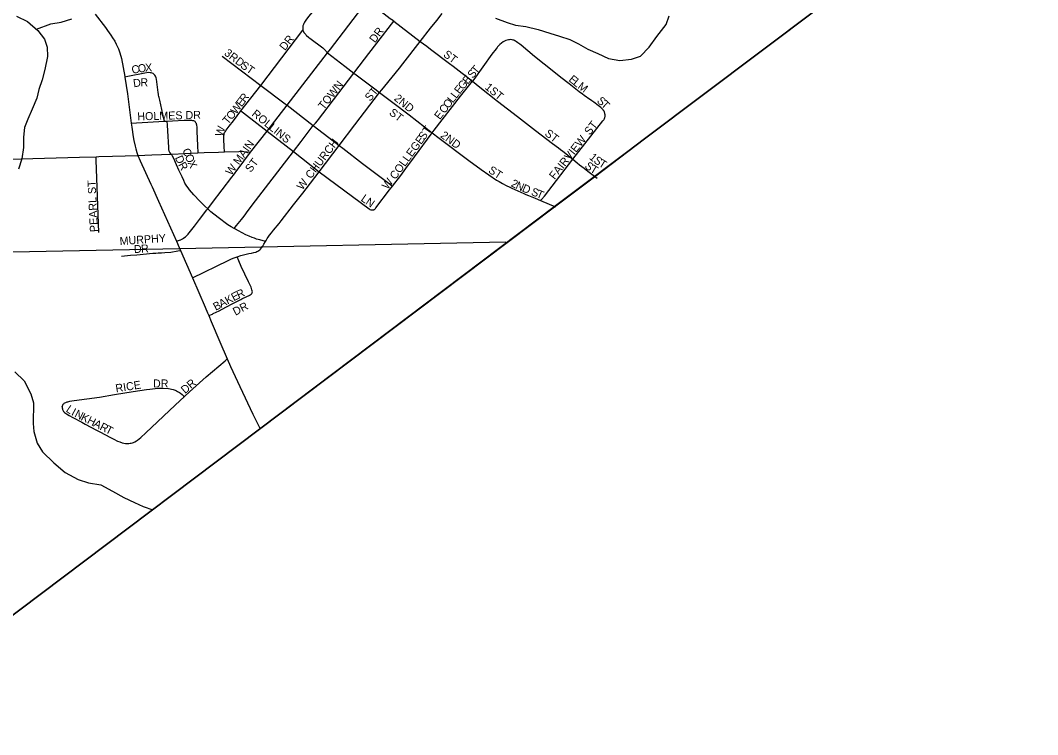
# Model space of a CAD drawing. Extents: x 1442749 to 1756758, y 235267 to 677782.
# Drawn here: x 1629919 to 1636274, y 480789 to 485248 of the extents above; entities that cross this region are included whole.
import ezdxf

# ---------------------------------------------------------------- set-up
doc = ezdxf.new("R2010")
doc.units = 0
for name, color, linetype in [('GM_X_Adjacent_County', 7, 'Continuous'), ('GM_X_City_Street', 7, 'Continuous'), ('GM_X_City_Street_Text', 7, 'Continuous'), ('GM_X_Corporation', 7, 'Continuous'), ('GM_X_County', 7, 'Continuous'), ('GM_X_Major_River', 7, 'Continuous'), ('GM_X_Minor_River', 7, 'Continuous'), ('GM_X_Rail_Line', 7, 'Continuous'), ('GM_X_State_Route', 7, 'Continuous'), ('GM_X_Township', 7, 'Continuous'), ('GM_X_Township_Subdivision', 7, 'Continuous'), ('GM_X_Township_Subdivision_Text', 7, 'Continuous')]:
    doc.layers.add(name, color=color, linetype=linetype)

msp = doc.modelspace()

# ---------------------------------------------------------------- linework, layer by layer
at = {"layer": 'GM_X_Adjacent_County'}
msp.add_lwpolyline([(1614699.6, 470049.9), (1618603.7, 472951.5), (1620523.4, 474378.3), (1621965.9, 475450.6), (1621996.8, 475474.4), (1628918.9, 480817.5), (1628957.6, 480847.4), (1631412.7, 482696.3), (1633247.9, 484078.4), (1633505.1, 484271.9), (1633818.5, 484508), (1635644.3, 485882.8), (1638041.6, 487688), (1640676.2, 489671.7), (1647133.1, 494533.2), (1648022.8, 495203.1), (1648788, 495779.1), (1655740.7, 500852.4)], dxfattribs=at)
at = {"layer": 'GM_X_City_Street'}
for points in [[(1631784.2, 485342.7), (1631744.4, 485301.8), (1631719.2, 485271.5), (1631703, 485250), (1631694.2, 485236.6), (1631690.1, 485228.8), (1631687.1, 485222.1), (1631684.3, 485213.1), (1631683.2, 485207.9), (1631682.8, 485203.8), (1631682.8, 485197.2), (1631683.9, 485187)], [(1631837.5, 485044.8), (1631855.8, 485068.1), (1632051.8, 485324.9), (1632086.5, 485369.8)], [(1632086.5, 485369.8), (1632229.8, 485260.8), (1632249.4, 485246.5), (1632252.4, 485244.1)], [(1632002.2, 484919), (1632007.7, 484926.3), (1632095.6, 485041.7), (1632252.4, 485244.1)], [(1632252.4, 485244.1), (1632416.9, 485116.8)], [(1631420.2, 484841.8), (1631683.9, 485187)], [(1631683.9, 485187), (1631687.8, 485178.6), (1631690.6, 485173.3), (1631692.1, 485171), (1631695.7, 485166.2), (1631697.7, 485163.7), (1631701.4, 485159.6), (1631705, 485155.9), (1631720.7, 485142.1), (1631727.9, 485136.4), (1631808.5, 485076), (1631815.3, 485069.9), (1631819.2, 485065.9), (1631837.5, 485044.8)], [(1632416.9, 485116.8), (1632457.5, 485086.9), (1632481.1, 485069.1), (1632598.8, 484979.3), (1632622.2, 484961.4), (1632742.7, 484867.9)], [(1632982.3, 485127.8), (1632974.7, 485127.7), (1632967.7, 485127.1), (1632959.3, 485125.5), (1632951.9, 485122.8), (1632943.5, 485118.4), (1632935.9, 485113.8), (1632924.6, 485105.7), (1632914.2, 485096.9), (1632908.6, 485091.5), (1632900.3, 485082.8), (1632896.8, 485079), (1632890.2, 485071.4), (1632863.9, 485037.6), (1632750.7, 484879), (1632742.7, 484867.9)], [(1633568.4, 484674), (1633567.6, 484676.2), (1633567.1, 484677.6), (1633566.5, 484679), (1633565.1, 484681.5), (1633564.3, 484683), (1633562.8, 484685.2), (1633562.1, 484686.2), (1633560.7, 484688.1), (1633559.5, 484689.7), (1633557, 484692.6), (1633554.1, 484695.6), (1633550.7, 484698.7), (1633545.2, 484703.3), (1633537.2, 484709.6), (1633529, 484715.9), (1633500.7, 484737.8), (1633488.8, 484746.4), (1633462.8, 484764.2), (1633455.5, 484769.2), (1633441, 484779.2), (1633430.6, 484786.7), (1633409, 484803), (1633346.6, 484851.3), (1633294.9, 484891.4), (1633251.4, 484926.1), (1633130.7, 485021.8), (1633047.7, 485092.7), (1633038.7, 485100.1), (1633027.5, 485108.7), (1633019.3, 485114.6), (1633012.4, 485119.1), (1633008.4, 485121.1), (1633001.5, 485123.9), (1632997.3, 485125.1), (1632991.2, 485126.6), (1632982.3, 485127.8)], [(1631179.2, 485024.9), (1631420.2, 484841.8)], [(1630819.3, 484618.3), (1630815.9, 484633.3), (1630789.1, 484750.1), (1630785.4, 484766.5), (1630783.8, 484773.9), (1630782.6, 484780.3), (1630781.5, 484786.6), (1630779.7, 484798.8), (1630768.2, 484880.9), (1630766.7, 484889.4), (1630765.3, 484894.8), (1630763, 484900.4), (1630759.4, 484906), (1630755.3, 484910.8), (1630751, 484914.4), (1630747.5, 484916.5), (1630742.1, 484918.8), (1630735.6, 484920.7), (1630729.9, 484921.6), (1630719.6, 484921.8), (1630697, 484918.4), (1630590.4, 484897.8), (1630572, 484894.3)], [(1631748.2, 484592.5), (1631761.9, 484606.7), (1631774.2, 484620.7), (1631781.8, 484630), (1631807.9, 484664.3), (1632002.2, 484919)], [(1631296, 484682.9), (1631420.2, 484841.8)], [(1631420.2, 484841.8), (1631572.1, 484727.7), (1631584.8, 484718.1)], [(1632491.4, 484546.3), (1632503.9, 484562.3), (1632668.8, 484774.1), (1632702, 484816.3), (1632742.7, 484867.9)], [(1632742.7, 484867.9), (1632789.1, 484831.3), (1632900.2, 484744.1), (1633024.9, 484647.8), (1633137.4, 484561), (1633242.8, 484479.1)], [(1631910.7, 484467), (1632007.5, 484596.1), (1632162.4, 484798.8)], [(1632162.4, 484798.8), (1632245.3, 484735.1), (1632347.4, 484658), (1632491.4, 484546.3)], [(1631584.8, 484718.1), (1631748.2, 484592.5)], [(1630836.4, 484619.2), (1630870.1, 484621), (1630941.8, 484624.2), (1630987.9, 484624.3), (1630994.5, 484623.6), (1630999.4, 484622), (1631003.8, 484620.6), (1631008.1, 484618.2), (1631011.2, 484614.6), (1631013.6, 484610.5), (1631016.1, 484606.3), (1631017.5, 484601.8), (1631019, 484597), (1631019.9, 484591), (1631020.8, 484584), (1631022.1, 484554.2), (1631026, 484466.1), (1631028, 484420.9)], [(1631193.7, 484427.2), (1631192.1, 484459.8), (1631189.9, 484504.3), (1631189.7, 484512.3), (1631189.7, 484518), (1631190.3, 484529.7), (1631191.2, 484536.3), (1631192.7, 484542), (1631194.7, 484547.3), (1631197.8, 484553), (1631201.4, 484558.4), (1631204.6, 484562.6), (1631210.9, 484570.3), (1631224, 484586.7), (1631250.5, 484621), (1631296, 484682.9)], [(1631296, 484682.9), (1631312.7, 484670), (1631459.9, 484556.3)], [(1630611.8, 484607.2), (1630643.4, 484608.8), (1630819.3, 484618.3)], [(1630819.3, 484618.3), (1630836.4, 484619.2)], [(1630860.4, 484413.1), (1630852.5, 484423.2), (1630848.5, 484432), (1630846.6, 484441.6), (1630845.3, 484454.6), (1630840.6, 484559.1), (1630838.2, 484594), (1630836.4, 484619.2)], [(1631625.6, 484430.2), (1631673.2, 484492.9), (1631748.2, 484592.5)], [(1631748.2, 484592.5), (1631873, 484496.5), (1631910.7, 484467)], [(1631459.9, 484556.3), (1631625.6, 484430.2)], [(1632244.5, 484213.7), (1632296.2, 484279.9), (1632325.9, 484322.9), (1632381.1, 484396.3), (1632491.4, 484546.3)], [(1632491.4, 484546.3), (1632534.2, 484513.1), (1632720.8, 484373.7), (1632797.2, 484317.1), (1632894.3, 484249.5)], [(1631785.9, 484301.6), (1631910.7, 484467)], [(1631910.7, 484467), (1631932.3, 484450.1), (1632057, 484354.4), (1632222, 484230.7), (1632244.5, 484213.7)], [(1630408.4, 483922.9), (1630392.4, 484375.8), (1630391.7, 484397)], [(1631089, 484071.8), (1631070.1, 484088.7), (1631039.9, 484118.6), (1631001.8, 484159.2), (1630976.3, 484189.3), (1630967.1, 484202), (1630958.9, 484213.1), (1630947.1, 484232.8), (1630940, 484247.5), (1630928.5, 484271.2), (1630909.7, 484313.2), (1630895, 484346.3), (1630877.6, 484385.2), (1630870.1, 484399.7), (1630864.3, 484408.5), (1630860.4, 484413.1)], [(1631089, 484071.8), (1631118.9, 484110.7), (1631240.3, 484268.9), (1631249.2, 484280.8), (1631261.3, 484297), (1631273.2, 484313.1), (1631357.1, 484425.9)], [(1631253.8, 483948.5), (1631269, 483967.3), (1631299.7, 484004.9), (1631308, 484015.7), (1631322.2, 484034.1), (1631331.4, 484046.2), (1631367.2, 484094.2), (1631449.8, 484202), (1631625.6, 484430.2)], [(1631625.6, 484430.2), (1631785.9, 484301.6)], [(1631450.4, 483868.1), (1631453.7, 483873.6), (1631461.4, 483885.9), (1631467.6, 483895.6), (1631475.6, 483906.9), (1631487.6, 483922.2), (1631500.9, 483939), (1631534.7, 483980.7), (1631548, 483997.5), (1631625.2, 484096.2), (1631683.5, 484169.7), (1631703.6, 484195.5), (1631785.9, 484301.6)], [(1631785.9, 484301.6), (1632098.6, 484070.8), (1632102.8, 484068.3), (1632107.6, 484066), (1632112.7, 484064.7), (1632116.2, 484064.4), (1632122.1, 484064.4)], [(1632122.1, 484064.4), (1632126.4, 484065.7), (1632129, 484066.8), (1632130.4, 484067.6), (1632132, 484068.7), (1632134, 484070.2), (1632135.7, 484071.7), (1632137.1, 484073.1), (1632140.1, 484076.9), (1632225.8, 484189.7), (1632244.5, 484213.7)], [(1630895, 483869), (1630913.8, 483876.1), (1630920.2, 483878.9), (1630923.8, 483880.6), (1630927.6, 483882.5), (1630932.6, 483885.2), (1630937.5, 483888.2), (1630940.5, 483890.3), (1630949.4, 483897), (1630953.7, 483900.7), (1630957.8, 483904.5), (1630962.4, 483909.2), (1630966.4, 483913.6), (1630970.9, 483918.7), (1630973.3, 483921.7), (1631006.1, 483964), (1631037.3, 484004.4), (1631083.7, 484064.9), (1631089, 484071.8)], [(1631253.8, 483948.5), (1631234.9, 483958.8), (1631215.6, 483971.1), (1631155.3, 484016.7), (1631109.2, 484053.8), (1631089, 484071.8)], [(1631450.4, 483868.1), (1631413.9, 483877.6), (1631394.8, 483882.6), (1631381.1, 483887.6), (1631367.1, 483892.8), (1631348.5, 483901.1), (1631328.1, 483910.2), (1631281.1, 483933.7), (1631261.8, 483944.2), (1631253.8, 483948.5)], [(1631273.2, 483772.8), (1631295.7, 483780.4), (1631312.7, 483785), (1631345.4, 483792.2), (1631362.3, 483795.6), (1631377.7, 483798.6), (1631388.8, 483801.8), (1631397, 483804.7), (1631402.1, 483807.2), (1631408.8, 483811.5), (1631413.7, 483815.5), (1631419.2, 483820.6), (1631425.4, 483827.9), (1631432.8, 483838.9), (1631439.8, 483850.2), (1631450.4, 483868.1)], [(1630551.5, 483775.9), (1630569, 483778.3), (1630587, 483780.7), (1630606.3, 483782.2), (1630645.6, 483785.2), (1630746.5, 483794), (1630765.2, 483795.1), (1630779.1, 483795.9), (1630800.8, 483797.2), (1630821.5, 483798.4), (1630858.9, 483801.8), (1630903.2, 483808.8), (1630920.1, 483811.5)], [(1630994, 483641.6), (1631217, 483748.9), (1631234.5, 483756.9), (1631248.3, 483763), (1631260.1, 483767.8), (1631272.2, 483772.5), (1631273.2, 483772.8)], [(1631095.3, 483404.9), (1631118.2, 483414.5), (1631124.2, 483417), (1631159.7, 483434), (1631179.8, 483444.8), (1631238.1, 483475.3), (1631296.2, 483506.4), (1631301.8, 483509.4), (1631307.3, 483512.1), (1631351.6, 483533.3), (1631355.3, 483535.1), (1631361.3, 483539), (1631364.8, 483542.4), (1631366.7, 483546.1), (1631367.8, 483549.2), (1631367.9, 483552.4), (1631367.2, 483558.7), (1631365.1, 483566.5), (1631363, 483574.6), (1631360.5, 483581.4), (1631357.4, 483589.9), (1631344.2, 483616.4), (1631298.8, 483711.1), (1631283.7, 483747.5), (1631273.2, 483772.8)], [(1630943.6, 482899.6), (1630975, 482928.5), (1631080.3, 483022.5), (1631197.5, 483122.9), (1631211.3, 483134.7)], [(1630180.6, 482834.8), (1630182.3, 482842.5), (1630183.6, 482846.6), (1630184.4, 482848.4), (1630186.8, 482852.2), (1630189.3, 482854.9), (1630192.9, 482858.1), (1630197.1, 482860.7), (1630202, 482863), (1630206, 482864.7), (1630211.5, 482866.6), (1630214.2, 482867.4), (1630221.5, 482869), (1630228.2, 482870.3), (1630239.4, 482872.1), (1630254.5, 482874.4), (1630413.6, 482896.6), (1630507.6, 482911.3), (1630624.3, 482930), (1630706.3, 482942.5), (1630727.6, 482945.2), (1630778, 482950.8), (1630797, 482951.8), (1630811, 482952.1), (1630844.6, 482949.4), (1630854.1, 482948), (1630863.5, 482946), (1630873.3, 482943.2), (1630886.4, 482938.6), (1630893.2, 482935.5), (1630900.8, 482931.5), (1630912.6, 482924.1), (1630918.4, 482919.9), (1630929, 482911.6), (1630937.2, 482904.8), (1630943.6, 482899.6)], [(1630180.6, 482834.8), (1630180.5, 482829.9), (1630180.8, 482826.1), (1630181.1, 482824.5), (1630181.7, 482821), (1630182.3, 482818.6), (1630183.4, 482815.5), (1630185.1, 482812), (1630188.7, 482806.7), (1630194.6, 482800.7), (1630206.4, 482791.4), (1630224, 482780.8), (1630246, 482768.6), (1630301.8, 482739.2), (1630324.5, 482727.2), (1630395.1, 482689.7), (1630414.2, 482679.5), (1630482.5, 482643.1), (1630501.8, 482633.4), (1630526.1, 482621.9), (1630540.8, 482616), (1630555, 482611.1), (1630575.1, 482607.4), (1630586.2, 482606.5), (1630596.8, 482606.8), (1630604.8, 482607.8), (1630611.4, 482609.1), (1630618.5, 482611.1), (1630625.2, 482613.6), (1630633.5, 482617.4), (1630644, 482623.1), (1630650.5, 482627.4), (1630660.3, 482634.9), (1630670.3, 482643.4), (1630701.7, 482673.2), (1630885.8, 482846.3), (1630943.6, 482899.6)]]:
    msp.add_lwpolyline(points, dxfattribs=at)
at = {"layer": 'GM_X_Corporation'}
msp.add_lwpolyline([(1635210.5, 485557.9), (1633823.1, 484511.4), (1633262.6, 484089.3), (1631412.7, 482696.3), (1628918.9, 480818.3), (1629029.5, 483037.3), (1629422.5, 483023.6), (1629418.1, 482896.7), (1629805, 482944.2), (1629128.1, 483732.4), (1629133.5, 483814.4), (1627617.6, 483785.3), (1627690.6, 485417.7)], dxfattribs=at)
at = {"layer": 'GM_X_County'}
msp.add_lwpolyline([(1655740.7, 500852.4), (1648788, 495779.1), (1648022.8, 495203.1), (1647133.1, 494533.2), (1640676.2, 489671.7), (1638041.6, 487688), (1635644.3, 485882.8), (1633818.5, 484508), (1633505.1, 484271.9), (1633247.9, 484078.4), (1631412.7, 482696.3), (1628957.6, 480847.4), (1628918.9, 480817.5), (1621996.8, 475474.4), (1621965.9, 475450.6), (1620523.4, 474378.3), (1618603.7, 472951.5), (1614699.6, 470049.9)], dxfattribs=at)
at = {"layer": 'GM_X_Major_River'}
for points in [[(1629893.5, 485273.8), (1629963.2, 485240.8), (1630028.5, 485185.9), (1630069.8, 485131.3), (1630087.1, 485081), (1630088.3, 485022.9), (1630071.2, 484941), (1630054.4, 484877.1), (1630033.5, 484817.3), (1630020.8, 484763.4), (1629991.8, 484693.6), (1629965, 484631.9), (1629944.3, 484580.1), (1629937.4, 484518.1), (1629938.6, 484454), (1629927.6, 484384), (1629906.7, 484318.2)], [(1629883.8, 483054.5), (1629943.1, 482997.7), (1629984, 482917), (1630001.3, 482860.7), (1629999.6, 482730.5), (1630002.9, 482680.4), (1630023.9, 482608), (1630057.2, 482553.5), (1630128.4, 482486.5), (1630197.6, 482425.5), (1630279.1, 482382.4), (1630344.9, 482361.5), (1630420.8, 482348.5), (1630494.3, 482309.5), (1630565.8, 482268.5), (1630631.5, 482237.6), (1630685.2, 482212.9), (1630745.2, 482192.1)]]:
    msp.add_lwpolyline(points, dxfattribs=at)
at = {"layer": 'GM_X_Minor_River'}
for points in [[(1630018.5, 485194.3), (1630108.8, 485225.8), (1630173, 485237.3), (1630239.3, 485258.7)], [(1632887.9, 485262.9), (1632959.8, 485234.2), (1633011.7, 485217.7), (1633075.7, 485209.1), (1633153.7, 485190.4), (1633225.6, 485167.7), (1633287.5, 485149.1), (1633351.5, 485128.5), (1633405.3, 485102), (1633463.1, 485069.4), (1633527, 485040.7), (1633592.8, 485010.1), (1633664.8, 484997.4), (1633737, 485006.8), (1633793.3, 485024.3), (1633847.9, 485081.9), (1633894.6, 485147.6), (1633953.4, 485223.3), (1633971.9, 485277.2)]]:
    msp.add_lwpolyline(points, dxfattribs=at)
at = {"layer": 'GM_X_Rail_Line'}
msp.add_lwpolyline([(1615664.4, 483549), (1619432.2, 483601), (1621936.9, 483649), (1626640.3, 483737.7), (1630912.8, 483823), (1632952.2, 483864.7)], dxfattribs=at)
at = {"layer": 'GM_X_State_Route'}
for points in [[(1630385, 485287.8), (1630450, 485203.5), (1630463.4, 485185.3), (1630483.5, 485156.8), (1630494.6, 485139.6), (1630507.8, 485117.7), (1630517.5, 485099.6), (1630531.5, 485070.1), (1630540.7, 485045.3), (1630549.9, 485010), (1630571.6, 484896.9), (1630572, 484894.3), (1630588, 484789.8), (1630603, 484672.8), (1630611.8, 484607.2), (1630615.1, 484581.8), (1630624.2, 484521.4), (1630628.4, 484498.4), (1630636, 484462.2), (1630640.2, 484445.4), (1630646.8, 484423), (1630652, 484405.1)], [(1632132.8, 484821), (1632162.4, 484798.8), (1632177.2, 484815.5), (1632195.7, 484836.4), (1632286.4, 484949.9), (1632307.5, 484976.9), (1632416.9, 485116.8), (1632481.2, 485199.1), (1632519.6, 485247.9), (1632552.9, 485291.1)], [(1631357.1, 484425.9), (1631459.9, 484556.3), (1631528.5, 484645), (1631584.8, 484718.1), (1631837.5, 485044.8)], [(1631837.5, 485044.8), (1631945.1, 484961.9), (1632002.2, 484919), (1632015.7, 484908.8), (1632132.8, 484821)], [(1631156.3, 484425.9), (1631193.7, 484427.2), (1631282.8, 484430.4), (1631290.9, 484430.7), (1631314, 484429.6), (1631357.1, 484425.9)], [(1629146, 484355.5), (1629213.5, 484358.1), (1629360.9, 484362), (1629563.9, 484370.7), (1629724.4, 484377.2), (1629924.4, 484383.2), (1630288.1, 484394.4), (1630391.7, 484397), (1630409.3, 484397.5), (1630494.5, 484400.3), (1630652, 484405.1), (1630740.3, 484407.8), (1630860.4, 484413.1), (1630864.7, 484413.3), (1631028, 484420.9), (1631067.8, 484422.8), (1631156.3, 484425.9)], [(1630652, 484405.1), (1630667.3, 484371.2), (1630734.4, 484225.1), (1630742, 484208.1), (1630782.1, 484119.2), (1630895, 483869), (1630911.7, 483830.6)], [(1630911.7, 483830.6), (1630920.1, 483811.5), (1630994, 483641.6), (1631073.7, 483457.1), (1631088.6, 483421.5), (1631095.3, 483404.9), (1631110.1, 483368.5), (1631165, 483240.2), (1631211.3, 483134.7), (1631232.3, 483086.9), (1631289.1, 482961.5)], [(1631289.1, 482961.5), (1631371.4, 482789), (1631416.4, 482697)]]:
    msp.add_lwpolyline(points, dxfattribs=at)
at = {"layer": 'GM_X_Township'}
msp.add_lwpolyline([(1642919, 502378.9), (1644427, 500258.8), (1647406, 496053.3), (1648022.8, 495203.1), (1647133.1, 494533.2), (1640676.2, 489671.7), (1638041.6, 487688), (1635644.3, 485882.8), (1633818.5, 484508), (1633505.1, 484271.9), (1633247.9, 484078.4), (1631412.7, 482696.3), (1628957.6, 480847.4), (1628918.9, 480817.5), (1621996.8, 475474.4), (1621965.9, 475450.6), (1620523.4, 474378.3), (1618603.7, 472951.5), (1618173.2, 474474.4), (1617334.6, 477440.8), (1616957.7, 478774.1)], dxfattribs=at)
at = {"layer": 'GM_X_Township_Subdivision'}
for points in [[(1633369.5, 484382.2), (1633558.5, 484620.4), (1633563.3, 484627), (1633565.9, 484631.1), (1633567.1, 484633.2), (1633567.8, 484634.8), (1633568.9, 484637.3), (1633569.5, 484638.8), (1633570.3, 484641.6), (1633570.9, 484644.3), (1633571.3, 484648), (1633571.5, 484652.8), (1633571.4, 484656.2), (1633571.2, 484660.1), (1633571, 484662.1), (1633570.6, 484665.3), (1633570.1, 484668.3), (1633568.4, 484674)], [(1633242.8, 484479.1), (1633280.5, 484452), (1633293.2, 484442.5), (1633308.6, 484430.8), (1633327.1, 484416.6), (1633352.4, 484396.3), (1633369.5, 484382.2)], [(1633168.3, 484123.5), (1633174.9, 484130.6), (1633194.2, 484151.4), (1633369.5, 484382.2)], [(1633369.5, 484382.2), (1633397.8, 484357.8), (1633412.4, 484346.1), (1633440.6, 484324.9), (1633464, 484307.3), (1633522.8, 484262.8)], [(1632894.3, 484249.5), (1632909.3, 484241.4), (1632931.7, 484229.2), (1632954.2, 484218), (1632975.6, 484207.2), (1632988.5, 484201.3), (1633064.8, 484166.4), (1633076.9, 484160.9), (1633093.6, 484154.1), (1633134.6, 484137.4), (1633168.3, 484123.5)], [(1633168.3, 484123.5), (1633262.4, 484084.7)]]:
    msp.add_lwpolyline(points, dxfattribs=at)

# ---------------------------------------------------------------- texts
at = {"layer": 'GM_X_City_Street_Text'}
for s, rotation, p in [('DR', 53.7411, (1632134.3, 485104)), ('DR', 51.33663, (1631571.3, 485055.9)), ('3RD', 322.69794, (1631188.4, 485035.5)), ('ST', 323.11554, (1632556.7, 485026.8)), ('C', 9.7098, (1630617.8, 484914.1)), ('O', 9.68511, (1630656.9, 484920.8)), ('X', 2.4924, (1630698.6, 484928)), ('ST', 325.30922, (1631289.2, 484956.6)), ('S', 49.21498, (1632744.5, 484882.1)), ('T', 49.24725, (1632767.5, 484908.8)), ('D', 8.51023, (1630626.8, 484830.1)), ('R', 0.55861, (1630668.5, 484836.4)), ('E', 49.29204, (1632712.9, 484845.4)), ('E', 320.9989, (1633340.3, 484872.5)), ('L', 320.9989, (1633367.6, 484850.3)), ('TOWN', 51.7627, (1631813.3, 484686.3)), ('ST', 50.19084, (1632103.8, 484739.3)), ('E', 52.01001, (1632663.5, 484784.4)), ('G', 50.2476, (1632685, 484811.8)), ('1ST', 320.19802, (1632816.7, 484824.1)), ('M', 322.91718, (1633396.4, 484827.1)), ('E', 53.12573, (1631300.9, 484704.1)), ('R', 53.11552, (1631322, 484732.3)), ('2ND', 321.00542, (1632249, 484753.8)), ('O', 52.11842, (1632593.3, 484694.1)), ('L', 52.10824, (1632620.3, 484728.8)), ('L', 52.11542, (1632641.9, 484756.6)), ('S', 318.44135, (1633516.4, 484740.4)), ('T', 316.66197, (1633542.4, 484717.3)), ('W', 53.11686, (1631266.5, 484658.3)), ('ROLLINS', 321.18523, (1631360.2, 484657)), ('ST', 322.4371, (1632218.4, 484663.7)), ('E', 52.10824, (1632539.3, 484624.6)), ('C', 52.1101, (1632569, 484662.8)), ('HOLMES DR', 1.4521, (1630649.9, 484623.8)), ('T', 50.10697, (1631215.2, 484594.3)), ('O', 52.26492, (1631239.1, 484622.9)), ('W', 72.92075, (1631181.5, 484518.2)), ('ST', 55.29785, (1632442.1, 484496.6)), ('ST', 322.42654, (1633190.4, 484533.9)), ('W MAIN', 53.97586, (1631236.4, 484276.4)), ('CHURCH', 52.73228, (1631734, 484255)), ('COLLEGE', 53.84329, (1632261.9, 484250.5)), ('2ND', 323.97381, (1632539, 484520.9)), ('C', 293.71838, (1630928.4, 484436.8)), ('D', 293.75831, (1630883.4, 484391.4)), ('O', 293.72015, (1630944.4, 484400.6)), ('X', 294.30919, (1630962.3, 484359.8)), ('ST', 52.42896, (1631357.8, 484294.9)), ('R', 297.87001, (1630902.8, 484347.6)), ('ST', 327.26793, (1632837.8, 484301.2)), ('PEARL ST', 92.72829, (1630403.3, 483927.6)), ('W', 53.9762, (1631681.3, 484184.7)), ('W', 53.98082, (1632213.4, 484188.6)), ('L', 324.90056, (1632041.7, 484124.9)), ('N', 325.155, (1632070.7, 484104.5)), ('MURPHY', 3.94622, (1630540.4, 483845.1)), ('D', 2.40505, (1630628.8, 483795.2)), ('R', 3.54924, (1630673.9, 483797.1)), ('E', 27.78467, (1631251.9, 483493.7)), ('R', 24.96848, (1631282.5, 483509.8)), ('B', 27.75967, (1631139, 483434.2)), ('A', 27.75752, (1631174, 483452.7)), ('K', 27.75752, (1631213, 483473.2)), ('DR', 27.89136, (1631262.1, 483403.6)), ('RICE', 8.88212, (1630516.8, 482925.4)), ('DR', 0.00001, (1630747.1, 482956.2)), ('DR', 40.59486, (1630947.9, 482914.3)), ('L', 326.1963, (1630199, 482808.3)), ('I', 331.98615, (1630233, 482785.9)), ('N', 332.79006, (1630253.1, 482775.2)), ('K', 333.04708, (1630292.4, 482754.9)), ('H', 333.02438, (1630331.6, 482735)), ('A', 333.0321, (1630370.8, 482715)), ('R', 333.03315, (1630410, 482695.1)), ('T', 333.01555, (1630445.3, 482677.1))]:
    msp.add_text(s, height=50, rotation=rotation, dxfattribs=at).set_placement(p)
at = {"layer": 'GM_X_Township_Subdivision_Text'}
for s, rotation, p in [('ST', 52.42653, (1633476.4, 484527.8)), ('FAIRVIEW', 51.60569, (1633256.5, 484250.7)), ('1', 320.01852, (1633468.8, 484386.6)), ('S', 324.51049, (1633495.8, 484364.2)), ('T', 328.09196, (1633527.3, 484341.8)), ('S', 322.69295, (1633440.4, 484330.9)), ('T', 329.47414, (1633473.7, 484305.9)), ('2', 334.77561, (1632979.4, 484213.7)), ('N', 336.2079, (1633008.5, 484200)), ('D', 336.43574, (1633049, 484182.2)), ('S', 339.07625, (1633105.4, 484158.9)), ('T', 337.64067, (1633137.9, 484146.4))]:
    msp.add_text(s, height=50, rotation=rotation, dxfattribs=at).set_placement(p)

doc.saveas('drawing.dxf')
